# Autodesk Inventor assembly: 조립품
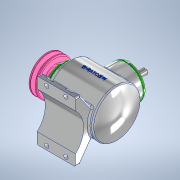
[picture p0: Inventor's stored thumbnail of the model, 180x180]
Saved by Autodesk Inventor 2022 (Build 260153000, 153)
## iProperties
Created: 2023-04
Part Number: 조립품
Document SubType Name: Assembly
Designer: Admin
Author: Admin
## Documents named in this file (17)
- C:\Users\Admin\Desktop\730411V1018\조립품.iam
- C:\Users\Admin\Desktop\730411V1018\본체.ipt
- C:\Users\Admin\Desktop\730411V1018\730411V1018\커버.ipt
- C:\Users\Admin\Desktop\730411V1018\730411V1018\베어링 6203.ipt
- C:\Users\Admin\Desktop\730411V1018\730411V1018\오일실 17 x 32 x 8.ipt
- C:\Users\Admin\Desktop\730411V1018\730411V1018\메인 축.ipt
- 메인 축.ipt
- C:\Users\Admin\Desktop\730411V1018\730411V1018\키 5 x 5 x 14.ipt
- C:\Users\Admin\Desktop\730411V1018\730411V1018\메인 베벨기어.ipt
- C:\Users\Admin\Desktop\730411V1018\730411V1018\서브 축.ipt
- 서브 축.ipt
- C:\Users\Admin\Desktop\730411V1018\730411V1018\키 4 x 4 x 14.ipt
- C:\Users\Admin\Desktop\730411V1018\730411V1018\서브 베벨기어.ipt
- C:\Users\Admin\Desktop\730411V1018\730411V1018\V-벨트풀리.ipt
- C:\Users\Admin\Desktop\730411V1018\730411V1018\볼트 M4 x 10.ipt
- C:\Users\Admin\Desktop\730411V1018\730411V1018\와셔 4 x 16.ipt
- C:\Users\Admin\Desktop\730411V1018\730411V1018\육각볼트 M4 x 8.ipt
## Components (1 placed, 1 different names)
1. V-벨트풀리:1
